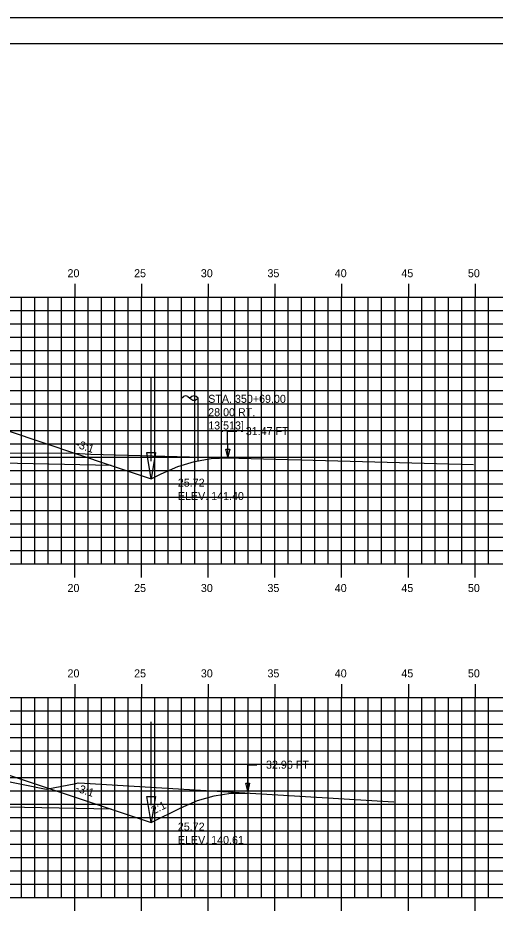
# Model space of a CAD drawing. Extents: x 1144529 to 1144699, y 608981 to 609091.
# Drawn here: x 1144627.6 to 1144663.4, y 609024.1 to 609091.3 of the extents above; entities that cross this region are included whole.
import ezdxf

# ---------------------------------------------------------------- set-up
doc = ezdxf.new("R2010")
doc.units = 0
for name, color, linetype in [('ANNOTATION', 7, 'Continuous'), ('BORDER', 7, 'Continuous'), ('D_Drainage_Ditch_Line', 7, 'Continuous'), ('D_Roadway_SlopeLines', 7, 'Continuous'), ('D_Roadway_SubGrade', 7, 'Continuous'), ('D_Text_Standard', 7, 'Continuous'), ('D_Utilities_Pole_Joint_Rt', 7, 'Continuous'), ('H_V ANNOTATION', 7, 'Continuous'), ('MAJOR', 7, 'Continuous'), ('MINOR', 7, 'Continuous'), ('PLOT BOUNDARY', 7, 'Continuous'), ('S_Roadway_Centerline', 7, 'Continuous')]:
    doc.layers.add(name, color=color, linetype=linetype)

msp = doc.modelspace()

# ---------------------------------------------------------------- linework, layer by layer
for points in [[(1144574.501, 609061.322), (1144575.751, 609061.235), (1144577.001, 609060.994), (1144578.251, 609060.599), (1144579.501, 609060.051), (1144586.138, 609056.732), (1144589.138, 609057.732), (1144596.861, 609060.307), (1144596.862, 609060.307), (1144600.862, 609060.467), (1144611.862, 609060.687), (1144622.862, 609060.467), (1144626.862, 609060.307), (1144634.586, 609057.732), (1144637.586, 609056.732), (1144638.331, 609057.105), (1144639.581, 609057.648), (1144640.831, 609058.025), (1144642.081, 609058.239), (1144643.331, 609058.287)], [(1144576.807, 609034.403), (1144578.057, 609034.307), (1144579.307, 609034.059), (1144580.557, 609033.661), (1144581.807, 609033.112), (1144586.138, 609030.946), (1144589.138, 609031.946), (1144596.861, 609034.521), (1144596.862, 609034.521), (1144600.862, 609034.681), (1144611.862, 609034.901), (1144622.862, 609034.681), (1144626.862, 609034.521), (1144634.586, 609031.946), (1144637.586, 609030.946), (1144639.82, 609032.063), (1144641.07, 609032.601), (1144642.32, 609032.963), (1144643.57, 609033.15), (1144644.82, 609033.162)]]:
    msp.add_lwpolyline(points)
at = {"layer": 'BORDER'}
msp.add_lwpolyline([(1144536.863, 608984.335), (1144696.863, 608984.335), (1144696.863, 609089.335), (1144536.863, 609089.335)], close=True, dxfattribs=at)
at = {"layer": 'D_Drainage_Ditch_Line'}
for p, q in [((1144637.586, 609058.045), (1144637.586, 609064.288)), ((1144637.586, 609032.259), (1144637.586, 609038.502))]:
    msp.add_line(p, q, dxfattribs=at)
for points in [[(1144637.258, 609058.701), (1144637.914, 609058.701), (1144637.586, 609056.732)], [(1144637.258, 609032.915), (1144637.914, 609032.915), (1144637.586, 609030.946)]]:
    msp.add_lwpolyline(points, close=True, dxfattribs=at)
at = {"layer": 'D_Roadway_SlopeLines'}
for points in [[(1144634.586, 609057.732), (1144637.586, 609056.732)], [(1144637.586, 609056.732), (1144638.331, 609057.105), (1144639.581, 609057.648), (1144640.831, 609058.025), (1144642.081, 609058.239), (1144643.331, 609058.287)], [(1144637.586, 609030.946), (1144639.82, 609032.063), (1144641.07, 609032.601), (1144642.32, 609032.963), (1144643.57, 609033.15), (1144644.82, 609033.162)], [(1144634.586, 609031.946), (1144637.586, 609030.946)]]:
    msp.add_lwpolyline(points, dxfattribs=at)
at = {"layer": 'D_Roadway_SubGrade'}
for points in [[(1144622.862, 609060.05), (1144622.862, 609060.217), (1144626.862, 609060.057), (1144626.862, 609060.307), (1144626.862, 609060.307), (1144634.586, 609057.732), (1144622.862, 609057.967)], [(1144622.862, 609034.264), (1144622.862, 609034.431), (1144626.862, 609034.271), (1144626.862, 609034.521), (1144626.862, 609034.521), (1144634.586, 609031.946), (1144622.862, 609032.181)]]:
    msp.add_lwpolyline(points, close=True, dxfattribs=at)
at = {"layer": 'D_Text_Standard'}
for points in [[(1144643.331, 609058.355), (1144643.316, 609060.299), (1144643.996, 609060.299)], [(1144644.82, 609033.313), (1144644.833, 609035.29), (1144645.513, 609035.29)]]:
    msp.add_lwpolyline(points, dxfattribs=at)
for points in [[(1144643.331, 609058.355), (1144643.181, 609058.936), (1144643.472, 609058.938)], [(1144644.82, 609033.313), (1144644.678, 609033.896), (1144644.969, 609033.894)]]:
    msp.add_lwpolyline(points, close=True, dxfattribs=at)
at = {"layer": 'D_Utilities_Pole_Joint_Rt'}
for p, q in [((1144639.862, 609062.777), (1144640.019, 609062.888)), ((1144639.862, 609058.02), (1144639.862, 609062.777)), ((1144640.331, 609062.888), (1144640.487, 609062.777)), ((1144640.643, 609062.888), (1144640.487, 609062.777)), ((1144640.487, 609062.777), (1144640.643, 609062.666)), ((1144641.112, 609062.777), (1144640.956, 609062.888)), ((1144640.956, 609062.666), (1144641.112, 609062.777)), ((1144641.112, 609058.02), (1144641.112, 609062.777))]:
    msp.add_line(p, q, dxfattribs=at)
for centre, start, end in [((1144640.175, 609062.667), 90, 125.26439), ((1144640.175, 609062.667), 54.73561, 90), ((1144640.8, 609062.667), 90, 125.26439), ((1144640.8, 609062.888), 234.73561, 270), ((1144640.8, 609062.667), 54.73561, 90), ((1144640.8, 609062.888), 270, 305.26439)]:
    msp.add_arc(centre, 0.271, start, end, dxfattribs=at)
at = {"layer": 'MAJOR'}
for p, q in [((1144631.862, 609071.337), (1144631.862, 609070.335)), ((1144636.862, 609071.337), (1144636.862, 609070.335)), ((1144641.862, 609071.337), (1144641.862, 609070.335)), ((1144646.862, 609071.337), (1144646.862, 609070.335)), ((1144651.862, 609071.337), (1144651.862, 609070.335)), ((1144656.862, 609071.337), (1144656.862, 609070.335)), ((1144661.862, 609071.337), (1144661.862, 609070.335)), ((1144541.862, 609070.335), (1144681.862, 609070.335)), ((1144541.862, 609070.335), (1144681.862, 609070.335)), ((1144631.862, 609050.335), (1144631.862, 609070.335)), ((1144636.862, 609050.335), (1144636.862, 609070.335)), ((1144641.862, 609050.335), (1144641.862, 609070.335)), ((1144646.862, 609050.335), (1144646.862, 609070.335)), ((1144651.862, 609050.335), (1144651.862, 609070.335)), ((1144656.862, 609050.335), (1144656.862, 609070.335)), ((1144661.862, 609050.335), (1144661.862, 609070.335)), ((1144541.862, 609065.335), (1144681.862, 609065.335)), ((1144541.862, 609060.335), (1144681.862, 609060.335)), ((1144541.862, 609055.335), (1144681.862, 609055.335)), ((1144541.862, 609050.335), (1144681.862, 609050.335)), ((1144541.862, 609050.335), (1144681.862, 609050.335)), ((1144631.862, 609049.333), (1144631.862, 609050.335)), ((1144636.862, 609049.333), (1144636.862, 609050.335)), ((1144641.862, 609049.333), (1144641.862, 609050.335)), ((1144646.862, 609049.333), (1144646.862, 609050.335)), ((1144651.862, 609049.333), (1144651.862, 609050.335)), ((1144656.862, 609049.333), (1144656.862, 609050.335)), ((1144661.862, 609049.333), (1144661.862, 609050.335)), ((1144631.862, 609041.337), (1144631.862, 609040.335)), ((1144636.862, 609041.337), (1144636.862, 609040.335)), ((1144641.862, 609041.337), (1144641.862, 609040.335)), ((1144646.862, 609041.337), (1144646.862, 609040.335)), ((1144651.862, 609041.337), (1144651.862, 609040.335)), ((1144656.862, 609041.337), (1144656.862, 609040.335)), ((1144661.862, 609041.337), (1144661.862, 609040.335)), ((1144541.862, 609040.335), (1144681.862, 609040.335)), ((1144541.862, 609040.335), (1144681.862, 609040.335)), ((1144631.862, 609025.335), (1144631.862, 609040.335)), ((1144636.862, 609025.335), (1144636.862, 609040.335)), ((1144641.862, 609025.335), (1144641.862, 609040.335)), ((1144646.862, 609025.335), (1144646.862, 609040.335)), ((1144651.862, 609025.335), (1144651.862, 609040.335)), ((1144656.862, 609025.335), (1144656.862, 609040.335)), ((1144661.862, 609025.335), (1144661.862, 609040.335)), ((1144541.862, 609035.335), (1144681.862, 609035.335)), ((1144541.862, 609030.335), (1144681.862, 609030.335)), ((1144541.862, 609025.335), (1144681.862, 609025.335)), ((1144541.862, 609025.335), (1144681.862, 609025.335)), ((1144631.862, 609024.333), (1144631.862, 609025.335)), ((1144636.862, 609024.333), (1144636.862, 609025.335)), ((1144641.862, 609024.333), (1144641.862, 609025.335)), ((1144646.862, 609024.333), (1144646.862, 609025.335)), ((1144651.862, 609024.333), (1144651.862, 609025.335)), ((1144656.862, 609024.333), (1144656.862, 609025.335)), ((1144661.862, 609024.333), (1144661.862, 609025.335))]:
    msp.add_line(p, q, dxfattribs=at)
at = {"layer": 'MINOR'}
for p, q in [((1144627.862, 609050.335), (1144627.862, 609070.335)), ((1144628.862, 609050.335), (1144628.862, 609070.335)), ((1144629.862, 609050.335), (1144629.862, 609070.335)), ((1144630.862, 609050.335), (1144630.862, 609070.335)), ((1144632.862, 609050.335), (1144632.862, 609070.335)), ((1144633.862, 609050.335), (1144633.862, 609070.335)), ((1144634.862, 609050.335), (1144634.862, 609070.335)), ((1144635.862, 609050.335), (1144635.862, 609070.335)), ((1144637.862, 609050.335), (1144637.862, 609070.335)), ((1144638.862, 609050.335), (1144638.862, 609070.335)), ((1144639.862, 609050.335), (1144639.862, 609070.335)), ((1144640.862, 609050.335), (1144640.862, 609070.335)), ((1144642.862, 609050.335), (1144642.862, 609070.335)), ((1144643.862, 609050.335), (1144643.862, 609070.335)), ((1144644.862, 609050.335), (1144644.862, 609070.335)), ((1144645.862, 609050.335), (1144645.862, 609070.335)), ((1144647.862, 609050.335), (1144647.862, 609070.335)), ((1144648.862, 609050.335), (1144648.862, 609070.335)), ((1144649.862, 609050.335), (1144649.862, 609070.335)), ((1144650.862, 609050.335), (1144650.862, 609070.335)), ((1144652.862, 609050.335), (1144652.862, 609070.335)), ((1144653.862, 609050.335), (1144653.862, 609070.335)), ((1144654.862, 609050.335), (1144654.862, 609070.335)), ((1144655.862, 609050.335), (1144655.862, 609070.335)), ((1144657.862, 609050.335), (1144657.862, 609070.335)), ((1144658.862, 609050.335), (1144658.862, 609070.335)), ((1144659.862, 609050.335), (1144659.862, 609070.335)), ((1144660.862, 609050.335), (1144660.862, 609070.335)), ((1144662.862, 609050.335), (1144662.862, 609070.335)), ((1144541.862, 609069.335), (1144681.862, 609069.335)), ((1144541.862, 609068.335), (1144681.862, 609068.335)), ((1144541.862, 609067.335), (1144681.862, 609067.335)), ((1144541.862, 609066.335), (1144681.862, 609066.335)), ((1144541.862, 609064.335), (1144681.862, 609064.335)), ((1144541.862, 609063.335), (1144681.862, 609063.335)), ((1144541.862, 609062.335), (1144681.862, 609062.335)), ((1144541.862, 609061.335), (1144681.862, 609061.335)), ((1144541.862, 609059.335), (1144681.862, 609059.335)), ((1144541.862, 609058.335), (1144681.862, 609058.335)), ((1144541.862, 609057.335), (1144681.862, 609057.335)), ((1144541.862, 609056.335), (1144681.862, 609056.335)), ((1144541.862, 609054.335), (1144681.862, 609054.335)), ((1144541.862, 609053.335), (1144681.862, 609053.335)), ((1144541.862, 609052.335), (1144681.862, 609052.335)), ((1144541.862, 609051.335), (1144681.862, 609051.335)), ((1144627.862, 609025.335), (1144627.862, 609040.335)), ((1144628.862, 609025.335), (1144628.862, 609040.335)), ((1144629.862, 609025.335), (1144629.862, 609040.335)), ((1144630.862, 609025.335), (1144630.862, 609040.335)), ((1144632.862, 609025.335), (1144632.862, 609040.335)), ((1144633.862, 609025.335), (1144633.862, 609040.335)), ((1144634.862, 609025.335), (1144634.862, 609040.335)), ((1144635.862, 609025.335), (1144635.862, 609040.335)), ((1144637.862, 609025.335), (1144637.862, 609040.335)), ((1144638.862, 609025.335), (1144638.862, 609040.335)), ((1144639.862, 609025.335), (1144639.862, 609040.335)), ((1144640.862, 609025.335), (1144640.862, 609040.335)), ((1144642.862, 609025.335), (1144642.862, 609040.335)), ((1144643.862, 609025.335), (1144643.862, 609040.335)), ((1144644.862, 609025.335), (1144644.862, 609040.335)), ((1144645.862, 609025.335), (1144645.862, 609040.335)), ((1144647.862, 609025.335), (1144647.862, 609040.335)), ((1144648.862, 609025.335), (1144648.862, 609040.335)), ((1144649.862, 609025.335), (1144649.862, 609040.335)), ((1144650.862, 609025.335), (1144650.862, 609040.335)), ((1144652.862, 609025.335), (1144652.862, 609040.335)), ((1144653.862, 609025.335), (1144653.862, 609040.335)), ((1144654.862, 609025.335), (1144654.862, 609040.335)), ((1144655.862, 609025.335), (1144655.862, 609040.335)), ((1144657.862, 609025.335), (1144657.862, 609040.335)), ((1144658.862, 609025.335), (1144658.862, 609040.335)), ((1144659.862, 609025.335), (1144659.862, 609040.335)), ((1144660.862, 609025.335), (1144660.862, 609040.335)), ((1144662.862, 609025.335), (1144662.862, 609040.335)), ((1144541.862, 609039.335), (1144681.862, 609039.335)), ((1144541.862, 609038.335), (1144681.862, 609038.335)), ((1144541.862, 609037.335), (1144681.862, 609037.335)), ((1144541.862, 609036.335), (1144681.862, 609036.335)), ((1144541.862, 609034.335), (1144681.862, 609034.335)), ((1144541.862, 609033.335), (1144681.862, 609033.335)), ((1144541.862, 609032.335), (1144681.862, 609032.335)), ((1144541.862, 609031.335), (1144681.862, 609031.335)), ((1144541.862, 609029.335), (1144681.862, 609029.335)), ((1144541.862, 609028.335), (1144681.862, 609028.335)), ((1144541.862, 609027.335), (1144681.862, 609027.335)), ((1144541.862, 609026.335), (1144681.862, 609026.335))]:
    msp.add_line(p, q, dxfattribs=at)
at = {"layer": 'PLOT BOUNDARY'}
msp.add_lwpolyline([(1144528.769, 608981.276), (1144698.769, 608981.276), (1144698.769, 609091.276), (1144528.769, 609091.276)], close=True, dxfattribs=at)
at = {"layer": 'S_Roadway_Centerline'}
for points in [[(1144563.592, 609061.416), (1144583.607, 609061.244), (1144583.773, 609061.241), (1144583.821, 609061.236), (1144592.307, 609059.29), (1144592.395, 609059.316), (1144595.656, 609060.163), (1144595.718, 609060.167), (1144597.643, 609060.351), (1144608.46, 609060.473), (1144608.57, 609060.475), (1144619.886, 609060.185), (1144620.036, 609060.18), (1144620.097, 609060.175), (1144623.583, 609059.807), (1144626.132, 609058.695), (1144626.261, 609058.67), (1144631.25, 609058.646), (1144631.393, 609058.672), (1144633.073, 609058.566), (1144661.744, 609057.785)], [(1144561.666, 609034.654), (1144561.946, 609034.651), (1144585.646, 609034.256), (1144592.503, 609033.516), (1144592.567, 609033.501), (1144595.079, 609034.252), (1144595.9, 609034.497), (1144595.906, 609034.498), (1144598.704, 609034.678), (1144598.944, 609034.678), (1144609.518, 609034.918), (1144620.904, 609034.561), (1144621.236, 609034.553), (1144621.437, 609034.537), (1144625.991, 609034.203), (1144626.131, 609034.175), (1144629.717, 609033.462), (1144631.943, 609033.887), (1144632.107, 609033.929), (1144632.595, 609033.902), (1144655.776, 609032.498)]]:
    msp.add_lwpolyline(points, dxfattribs=at)

# ---------------------------------------------------------------- texts
at = {"layer": 'ANNOTATION'}
for s, rotation, p in [('-3:1', 341.56521, (1144631.874, 609059.091)), ('-3:1', 341.56521, (1144631.874, 609033.304)), ('2:1', 26.56505, (1144637.775, 609031.559))]:
    msp.add_text(s, height=0.6, rotation=rotation, dxfattribs=at).set_placement(p)
at = {"layer": 'D_Text_Standard'}
for s, p in [('STA. 350+69.00', (1144641.862, 609062.418)), ('28.00 RT.', (1144641.862, 609061.416)), ('13[513] ', (1144641.862, 609060.42)), ('31.47 FT', (1144644.676, 609059.999)), ('25.72', (1144639.586, 609056.132)), ('ELEV. 141.40', (1144639.586, 609055.13)), ('32.96 FT', (1144646.193, 609034.99)), ('25.72', (1144639.586, 609030.346)), ('ELEV. 140.61', (1144639.586, 609029.344))]:
    msp.add_text(s, height=0.6, dxfattribs=at).set_placement(p)
at = {"layer": 'H_V ANNOTATION'}
for s, p in [('20', (1144631.316, 609071.835)), ('25', (1144636.308, 609071.835)), ('30', (1144641.311, 609071.835)), ('35', (1144646.303, 609071.835)), ('40', (1144651.348, 609071.835)), ('45', (1144656.34, 609071.835)), ('50', (1144661.327, 609071.835)), ('20', (1144631.316, 609048.235)), ('25', (1144636.308, 609048.235)), ('30', (1144641.311, 609048.235)), ('35', (1144646.303, 609048.235)), ('40', (1144651.348, 609048.235)), ('45', (1144656.34, 609048.235)), ('50', (1144661.327, 609048.235)), ('20', (1144631.316, 609041.835)), ('25', (1144636.308, 609041.835)), ('30', (1144641.311, 609041.835)), ('35', (1144646.303, 609041.835)), ('40', (1144651.348, 609041.835)), ('45', (1144656.34, 609041.835)), ('50', (1144661.327, 609041.835))]:
    msp.add_text(s, height=0.6, dxfattribs=at).set_placement(p)

doc.saveas('drawing.dxf')
